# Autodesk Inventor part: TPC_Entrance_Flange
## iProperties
Shininess: 64.0
Length Units: 11269
Angle Units: 11279
Time Units: 11290
Mass Units: 11283
Length Display Precision: 3
Angle Display Precision: 2
Compacted: True
Part Number: TPC_Entrance_Flange
Document SubType Name: Modeling
Created: 2004-07
Designer: John Blackburn
Manufacturer: Standard
Standards Organization: Custom
Material: Stainless Steel, Austenitic
Description: Mucap, Entrance Flange
Density: 0.0
Volumn: 0.0
Area: 0.0
PropertySet Name: Model Information
Control State: 0
Master: False
Checked Out: False
Author: John Blackburn
Title: TPC Entrance Flange
Subject: MuCap
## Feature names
1. Extrusion1
2. Hole1
3. Circular Pattern1
4. Extrusion2
5. Chamfer1
6. Hole2
7. Circular Pattern2
8. Hole3
9. Circular Pattern3
10. Hole4
11. Hole5
12. Extrusion3
13. Extrusion4
14. Extrusion5
15. Hole6
